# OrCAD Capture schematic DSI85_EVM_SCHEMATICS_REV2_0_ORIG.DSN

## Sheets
1 PAGE01 Title Page: title: PAGE01 SN65DSI85 EVM Schematics Block Diagram; rev: v2.0; note: YJL_DSI85EVM_rev2_0
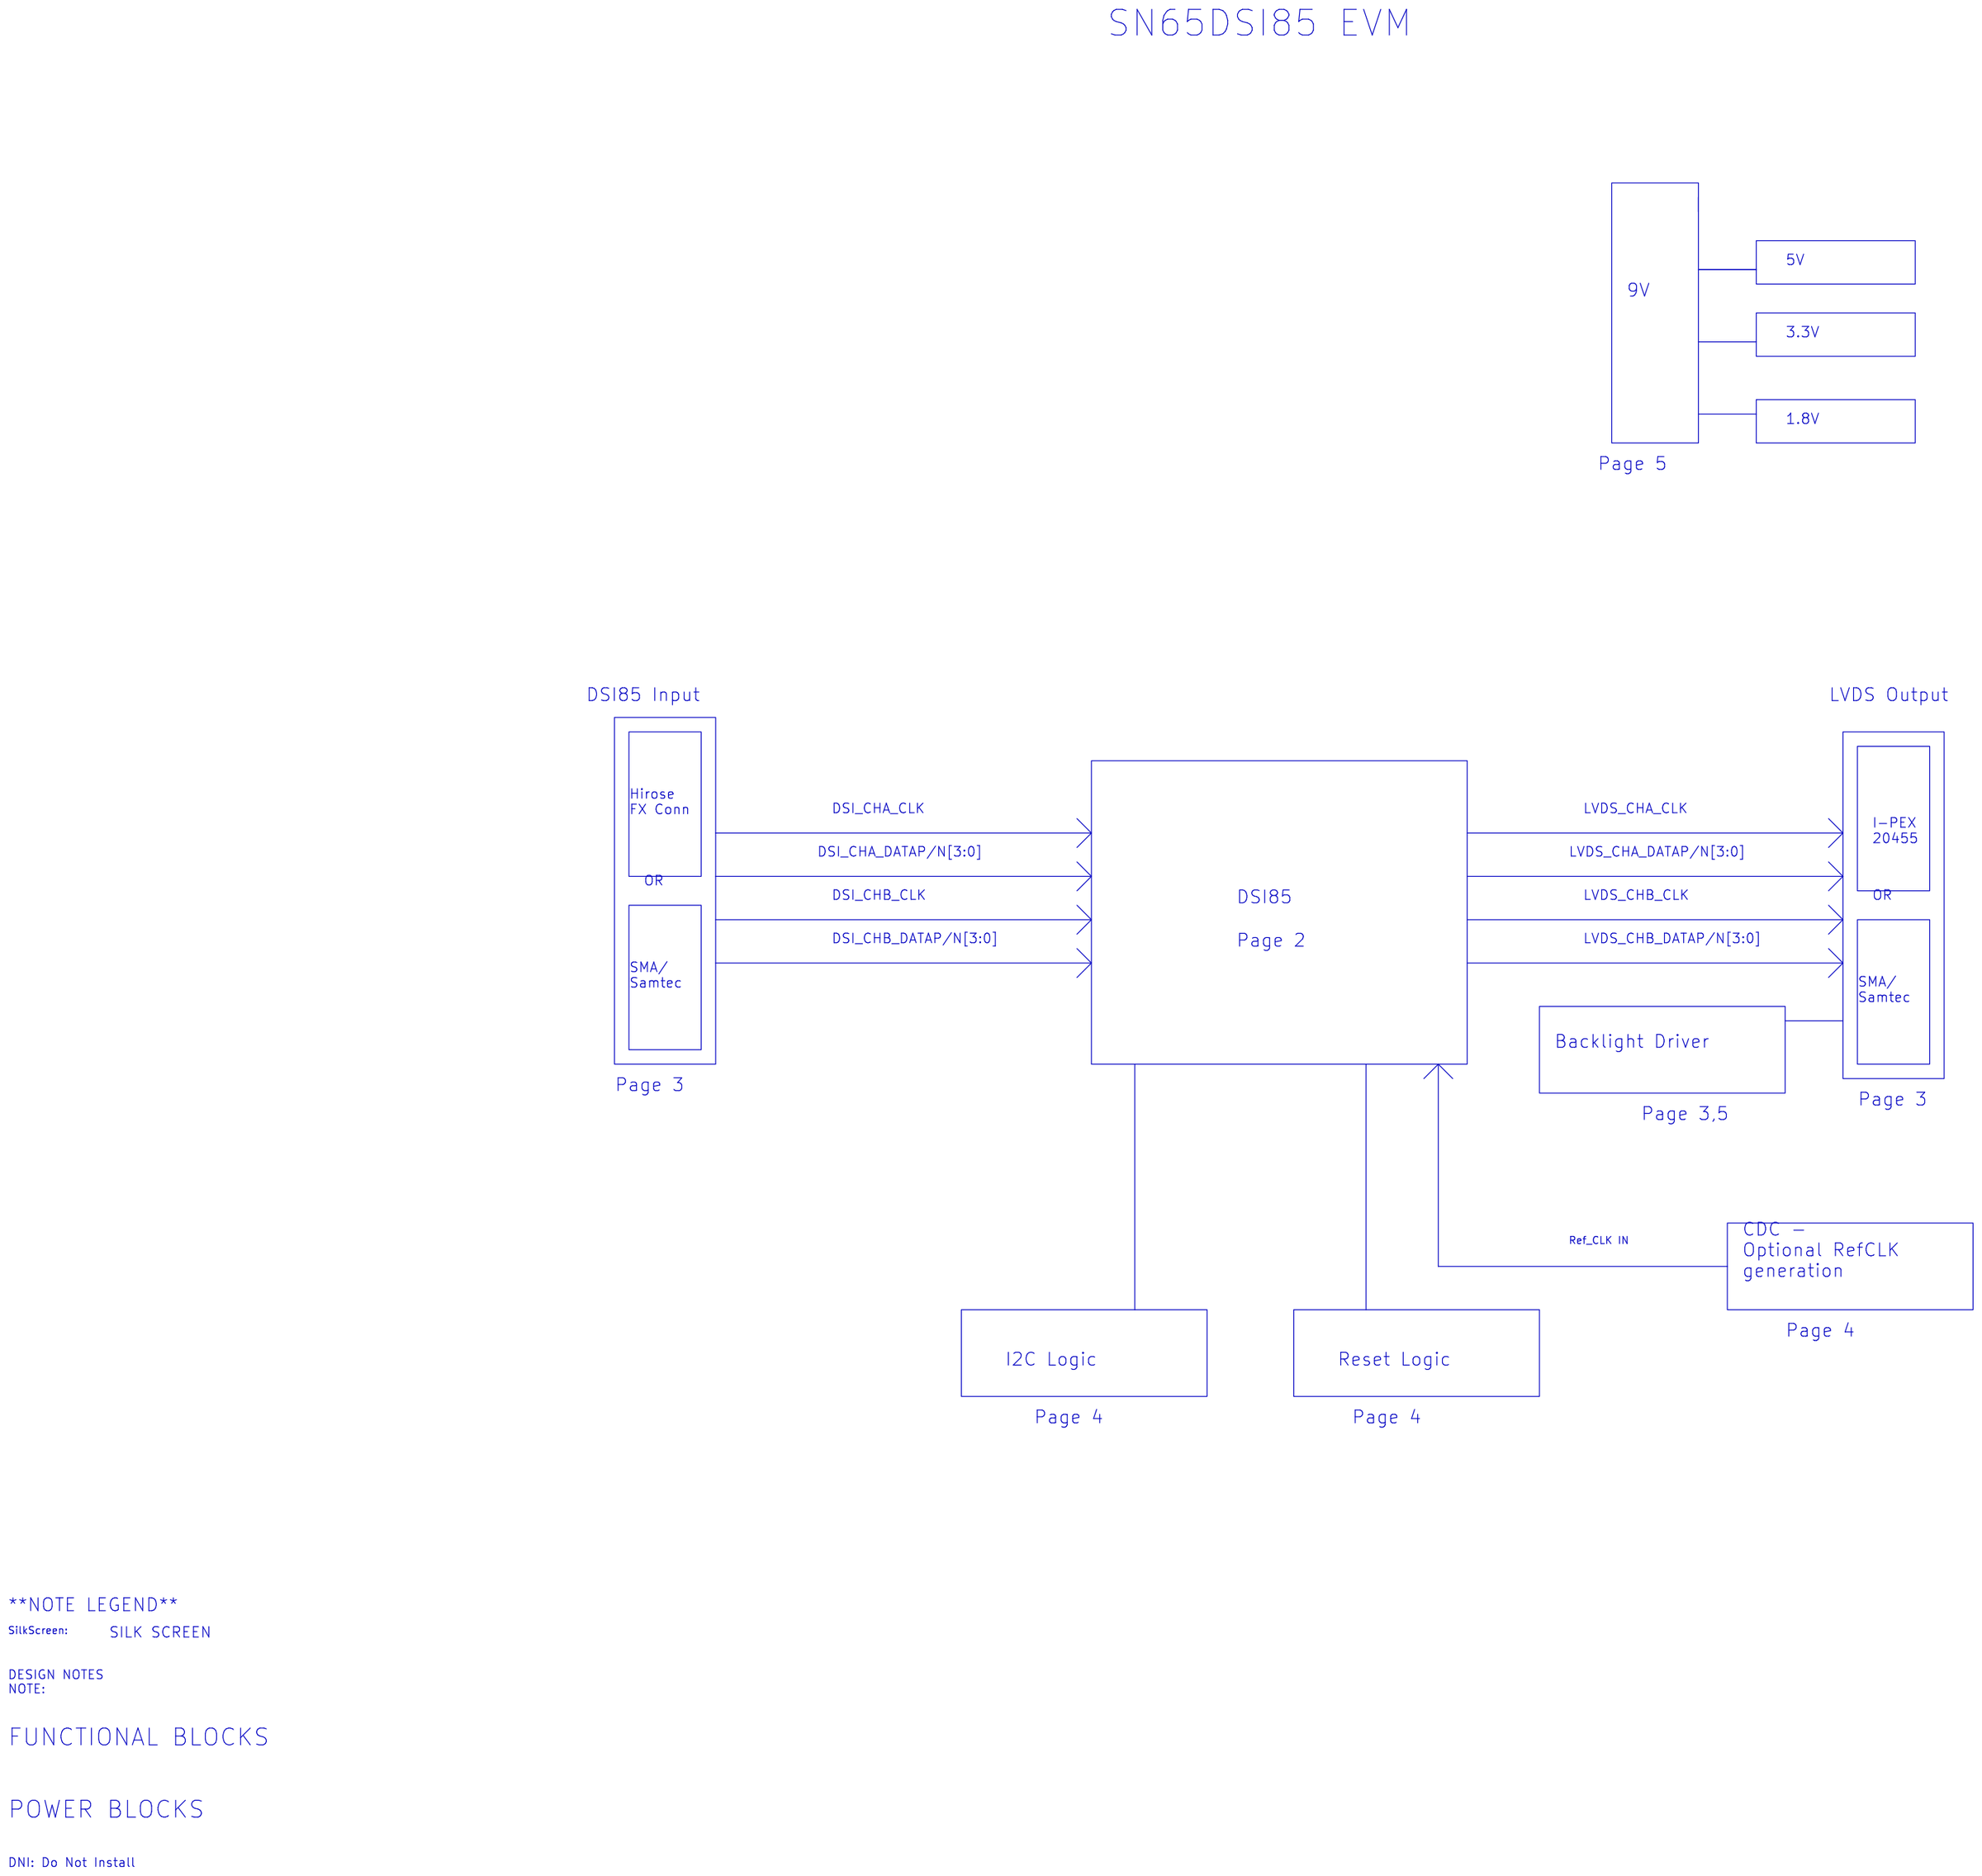
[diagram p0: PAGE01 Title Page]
2 PAGE02 DSI85: size C; title: PAGE02 SN65DSI85; note: Preliminary
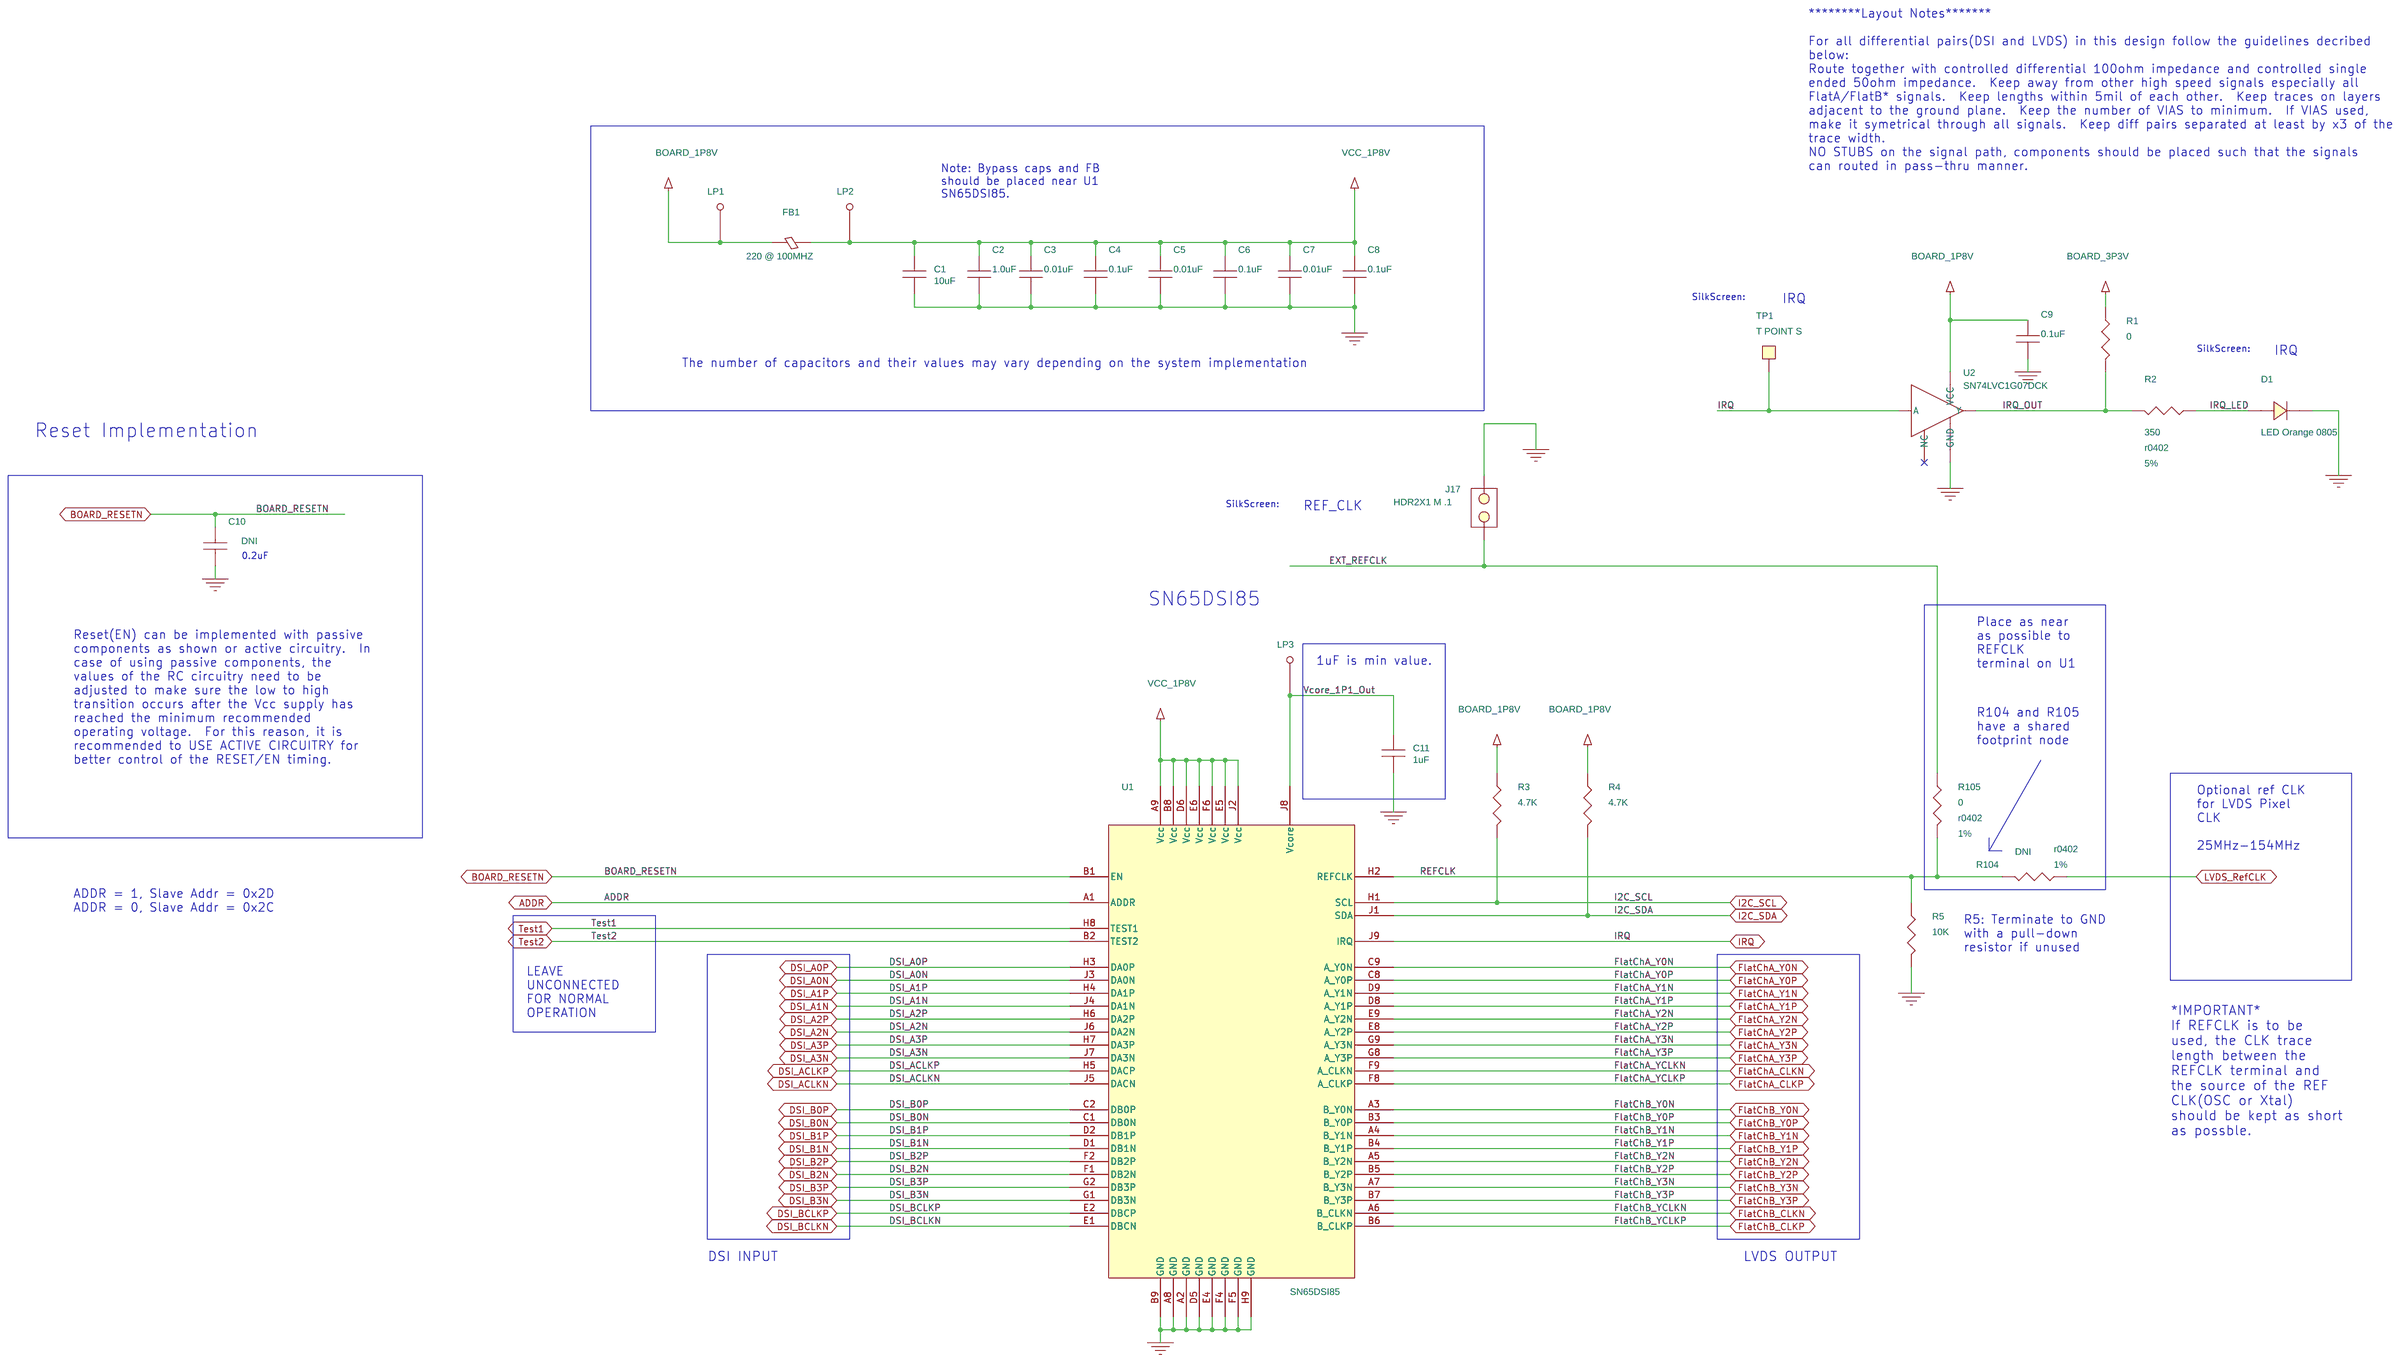
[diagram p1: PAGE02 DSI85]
3 PAGE03 Connectors: size C; title: PAGE03 Connectors
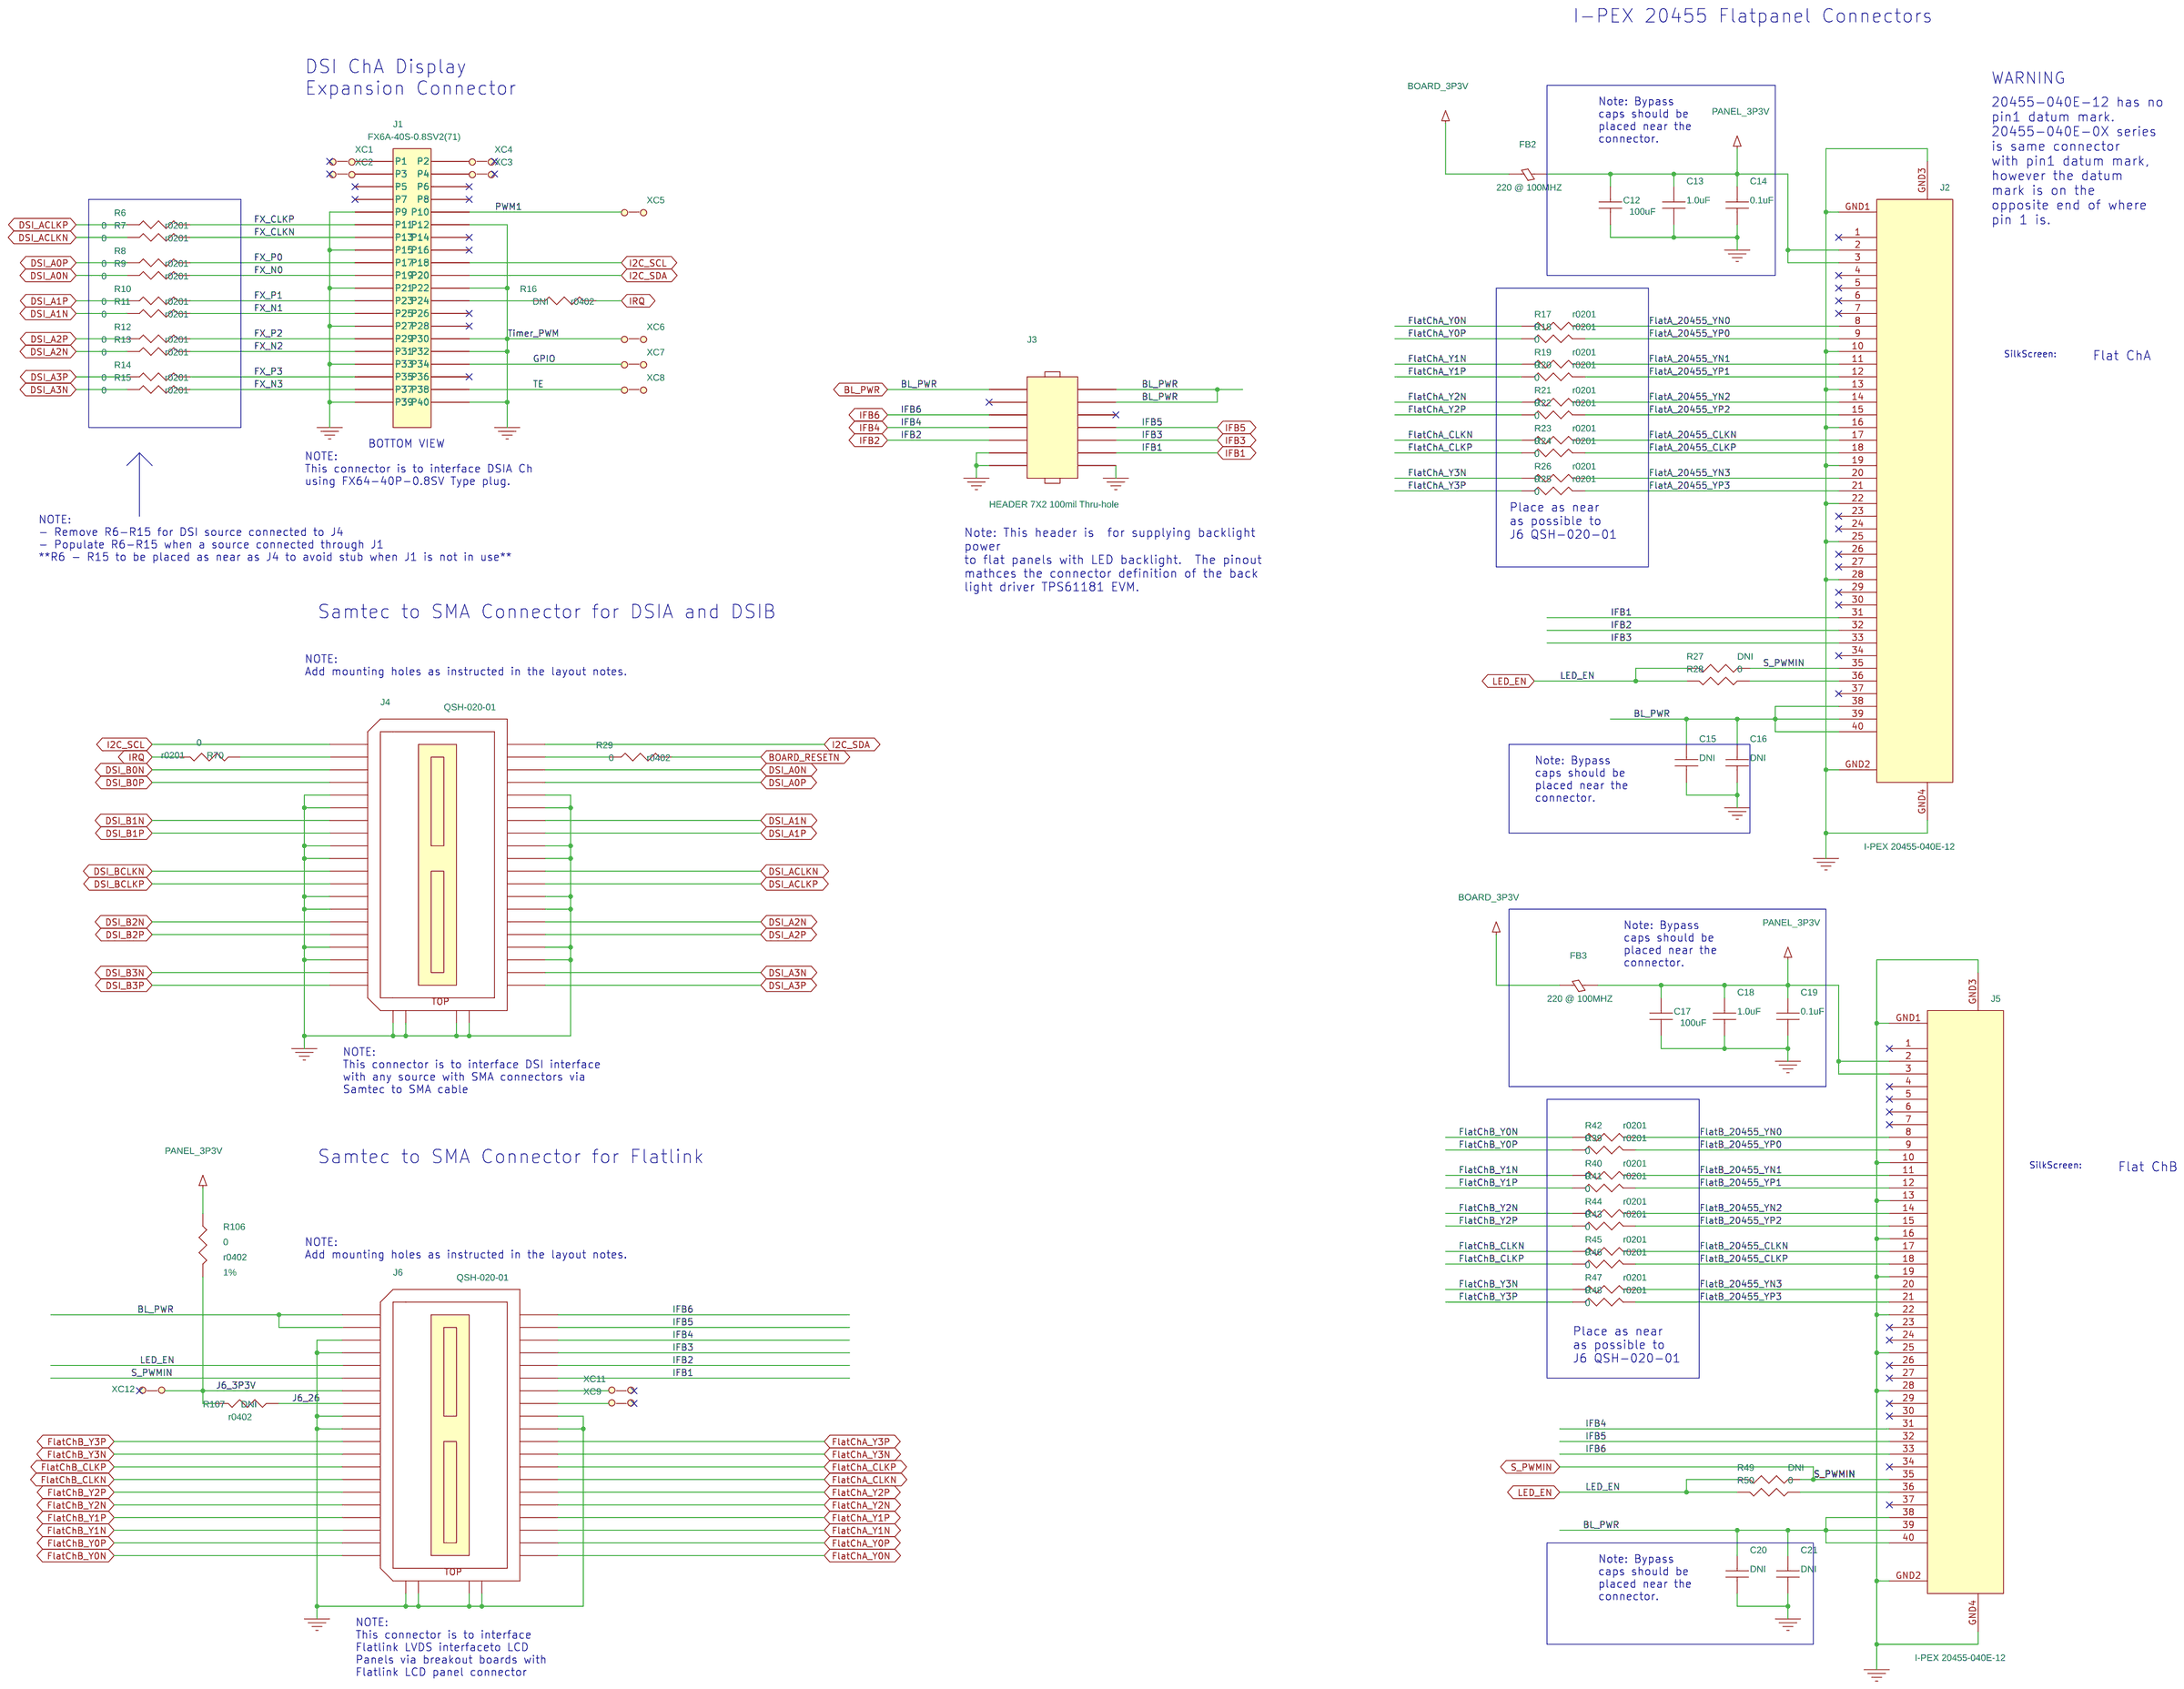
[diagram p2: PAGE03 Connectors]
4 PAGE04 Reset_CDC: size C; title: PAGE04 RESET_CDC
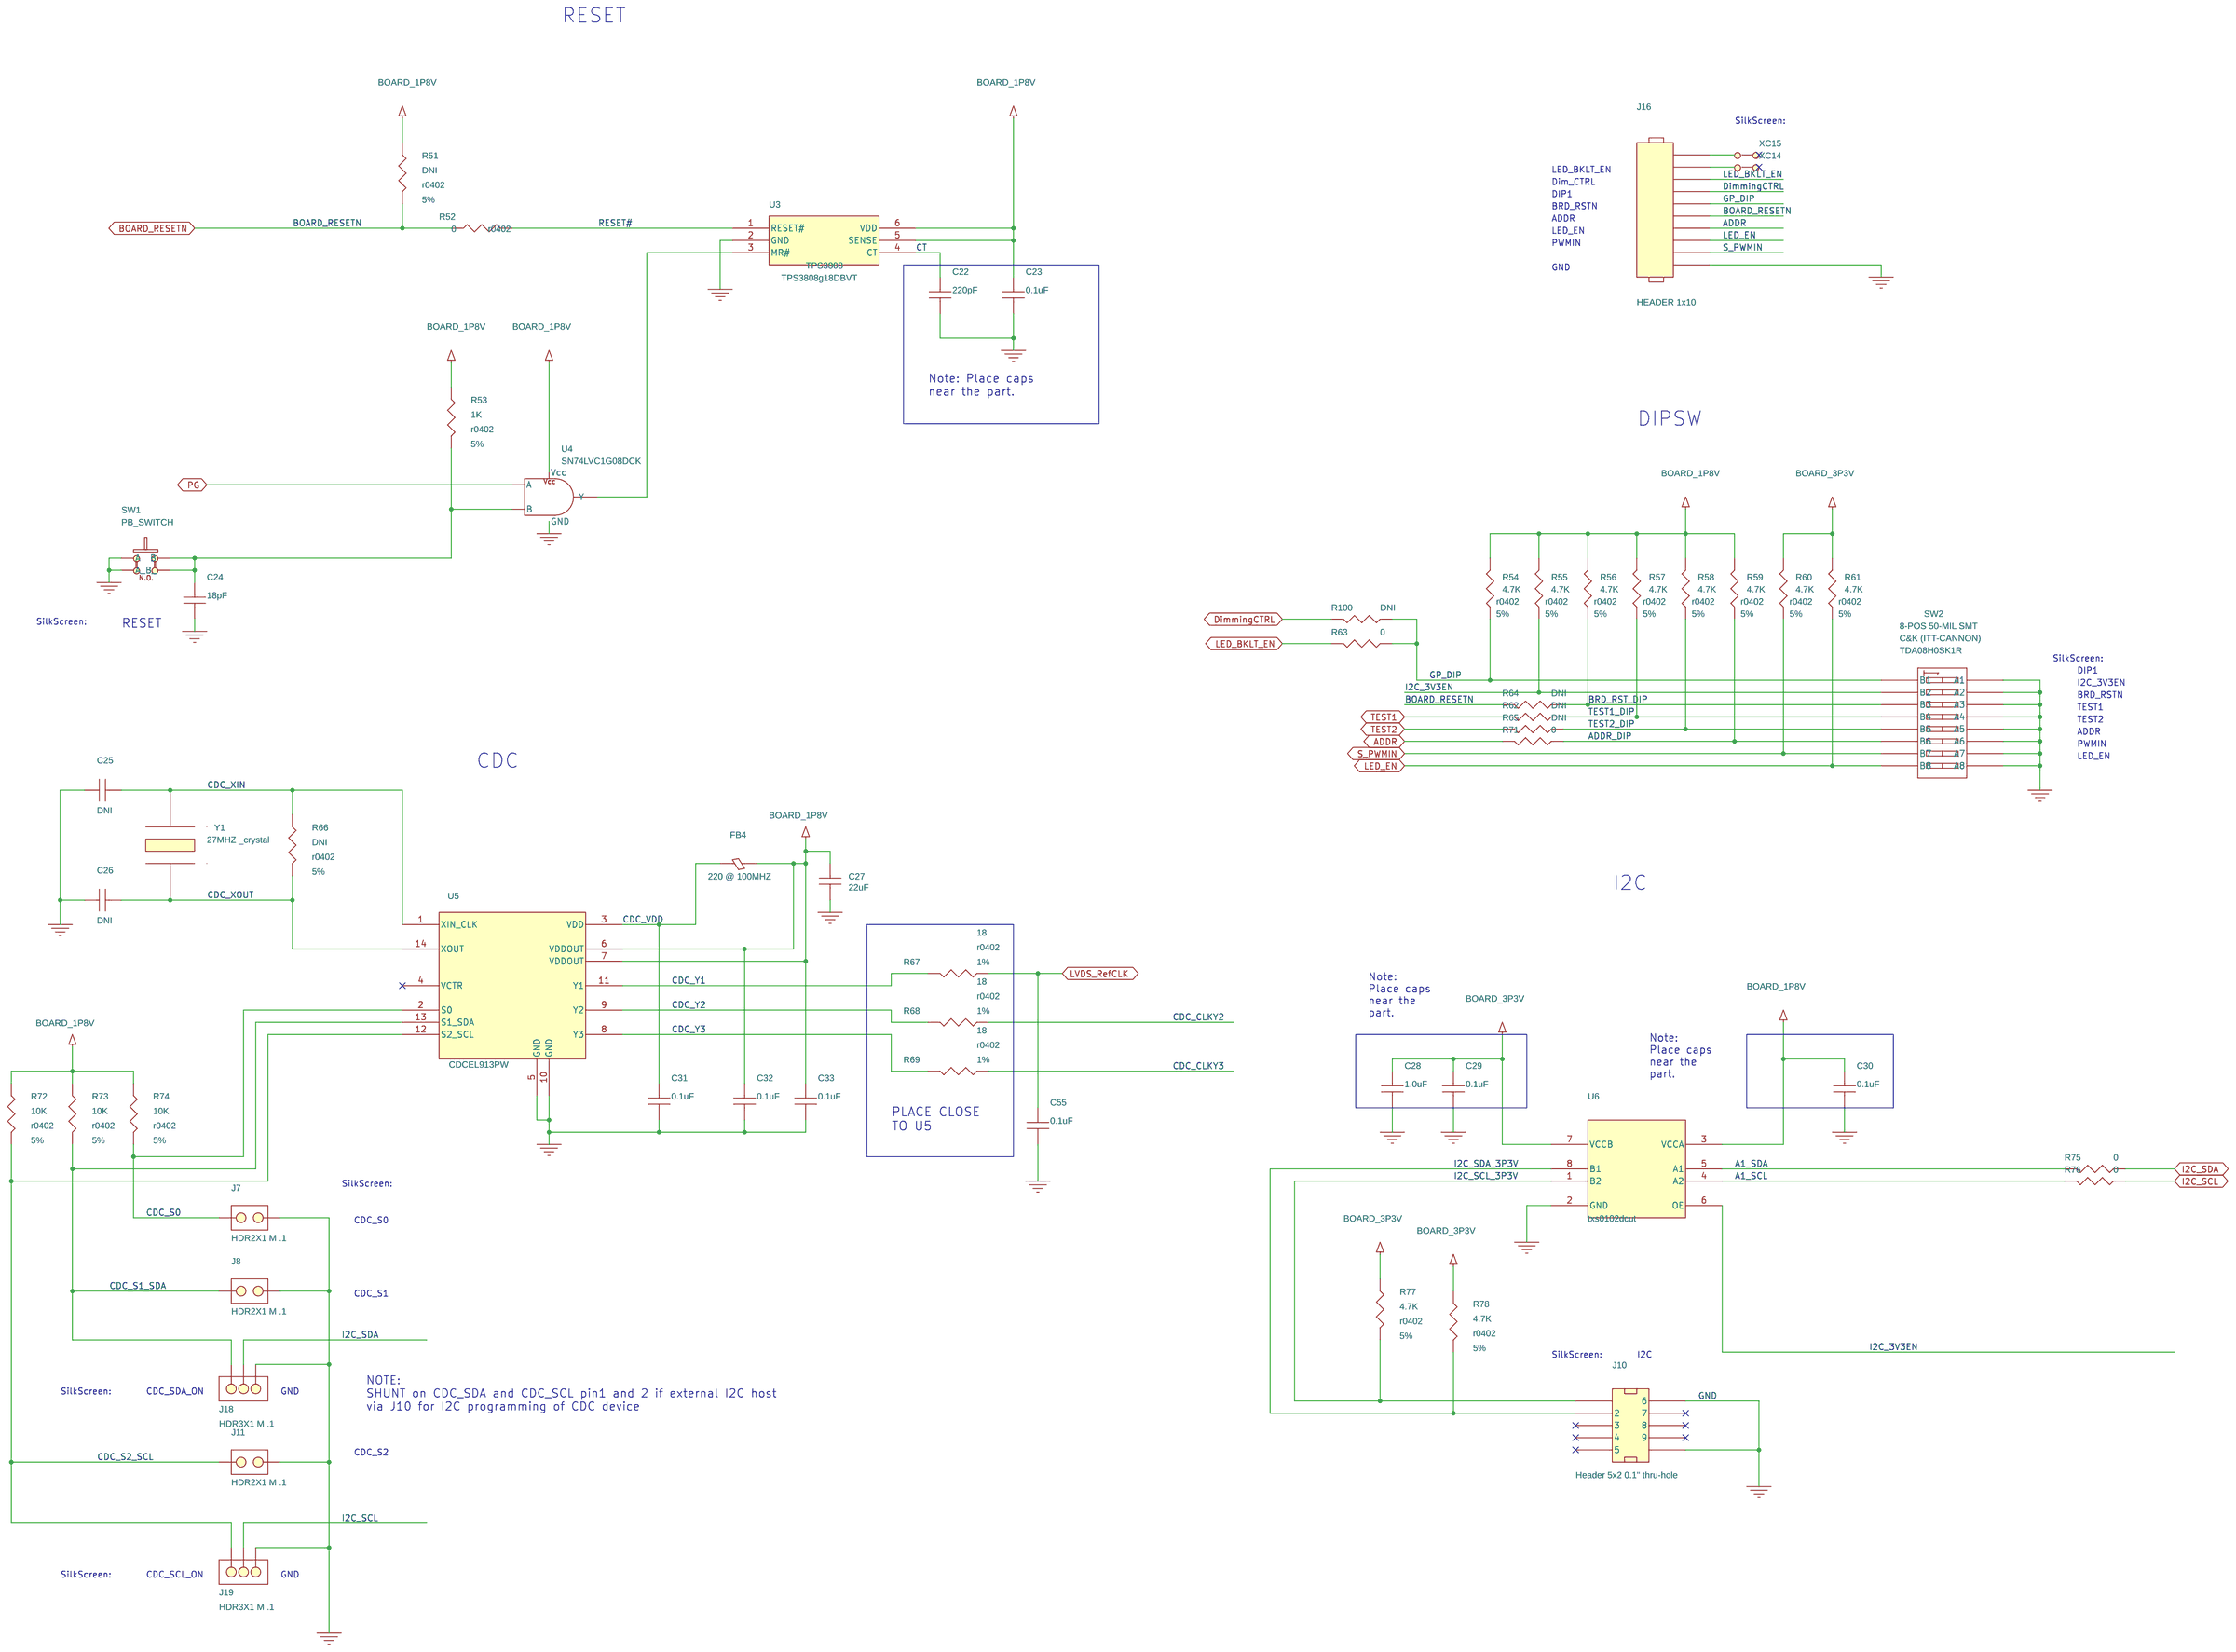
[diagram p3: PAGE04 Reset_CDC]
5 PAGE05 Power: size C; title: PAGE05 Power
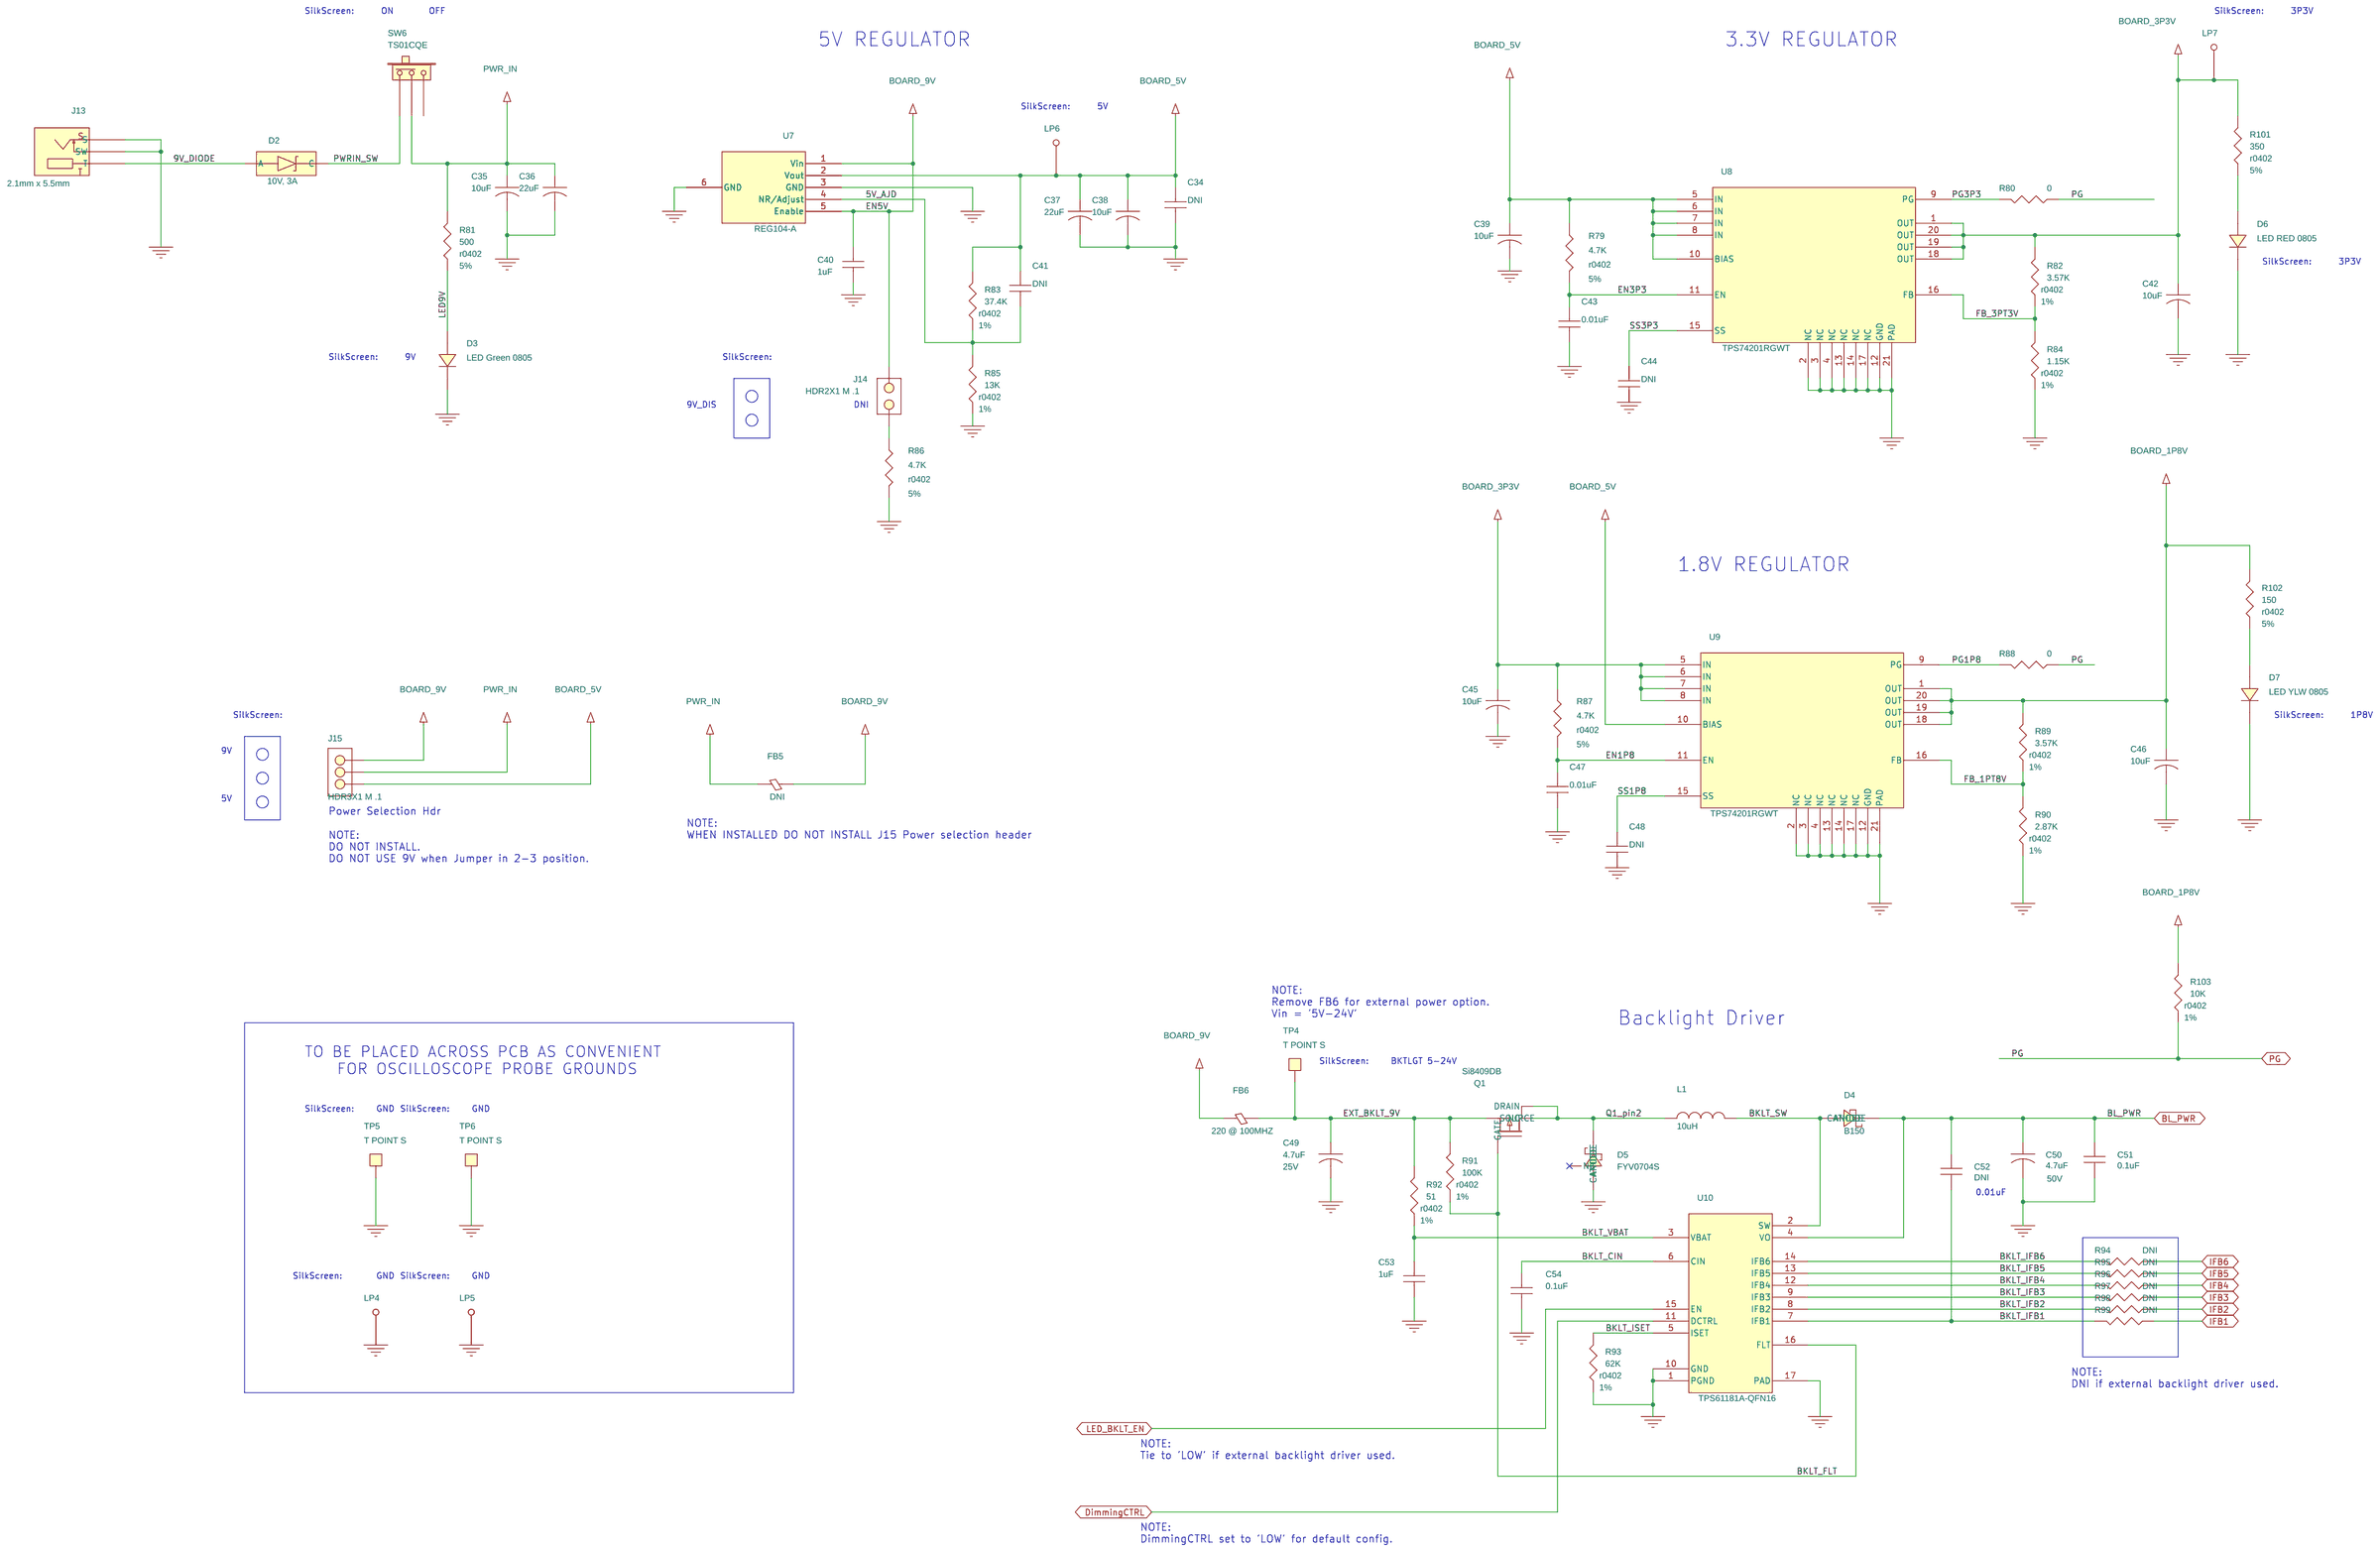
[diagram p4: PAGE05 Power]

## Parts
sheet PAGE02 DSI85
C1  10uF  [cc0805]
C2  1.0uF  [cc0402]
C3  0.01uF  [cc0201]
C4  0.1uF  [cc0201]
C5  0.01uF  [cc0201]
C6  0.1uF  [cc0201]
C7  0.01uF  [cc0201]
C8  0.1uF  [cc0201]
C9  0.1uF  [cc0201]
C10  DNI  [cc0201]
C11  1uF  [cc0603]
D1  LED Orange 0805  [cc0805]
FB1  220 @ 100MHZ  [r0603]
J17  HDR2X1 M .1  [berg1x2]
LP1  LP  [TESTLOOP]
LP2  LP  [TESTLOOP]
LP3  LP  [TESTLOOP]
R1  0  [r0402]
R2  350  [r0402]
R3  4.7K  [r0402]
R4  4.7K  [r0402]
R5  10K  [r0402]
R104  DNI  [r0402]
R105  0  [r0402]
TP1  T POINT S  [berg1x1]
U1  SN65DSI85  [Ironwood_81pin_7048]
U2  SN74LVC1G07DCK  [DCK5]
sheet PAGE03 Connectors
C12  100uF  [CC6032]
C13  1.0uF  [cc0402]
C14  0.1uF  [cc0402]
C15  DNI  [cc0603]
C16  DNI  [cc0603]
C17  100uF  [CC6032]
C18  1.0uF  [cc0402]
C19  0.1uF  [cc0402]
C20  DNI  [cc0603]
C21  DNI  [cc0603]
FB2  220 @ 100MHZ  [r0603]
FB3  220 @ 100MHZ  [r0603]
J1  FX6A-40S-0.8SV2(71)  [IPEX_20006_40pin]
J2  I-PEX 20455-040E-12  [ipex_20455_40pin]
J3  HEADER 7X2 100mil Thru-hole  [berg2x7]
J4  QSH-020-01  [QSH-020_x]
J5  I-PEX 20455-040E-12  [ipex_20455_40pin]
J6  QSH-020-01  [QSH-020_x]
R6  0  [r0201]
R7  0  [r0201]
R8  0  [r0201]
R9  0  [r0201]
R10  0  [r0201]
R11  0  [r0201]
R12  0  [r0201]
R13  0  [r0201]
R14  0  [r0201]
R15  0  [r0201]
R16  DNI  [r0402]
R17  0  [r0201]
R18  0  [r0201]
R19  0  [r0201]
R20  0  [r0201]
R21  0  [r0201]
R22  0  [r0201]
R23  0  [r0201]
R24  0  [r0201]
R25  0  [r0201]
R26  0  [r0201]
R27  DNI  [r0402]
R28  0  [r0402]
R29  0  [r0402]
R39  0  [r0201]
R40  0  [r0201]
R41  0  [r0201]
R42  0  [r0201]
R43  0  [r0201]
R44  0  [r0201]
R45  0  [r0201]
R46  0  [r0201]
R47  0  [r0201]
R48  0  [r0201]
R49  DNI  [r0402]
R50  0  [r0402]
R70  0  [r0201]
R106  0  [r0402]
R107  DNI  [r0402]
XC1  XC  [jmp_2p]
XC2  XC  [jmp_2p]
XC3  XC  [jmp_2p]
XC4  XC  [jmp_2p]
XC5  XC  [jmp_2p]
XC6  XC  [jmp_2p]
XC7  XC  [jmp_2p]
XC8  XC  [jmp_2p]
XC9  XC  [jmp_2p]
XC11  XC  [jmp_2p]
XC12  XC  [jmp_2p]
sheet PAGE04 Reset_CDC
C22  220pF  [cc0402]
C23  0.1uF  [cc0402]
C24  18pF  [cc0402]
C25  DNI  [cc0402]
C26  DNI  [cc0402]
C27  22uF  [cc0805]
C28  1.0uF  [cc0402]
C29  0.1uF  [cc0402]
C30  0.1uF  [cc0402]
C31  0.1uF  [cc0402]
C32  0.1uF  [cc0402]
C33  0.1uF  [cc0402]
C55  0.1uF  [cc0402]
FB4  220 @ 100MHZ  [r0603]
J7  HDR2X1 M .1  [HDR_2x1]
J8  HDR2X1 M .1  [HDR_2x1]
J10  Header 5x2 0.1" thru-hole  [berg2x5]
J11  HDR2X1 M .1  [HDR_2x1]
J16  HEADER 1x10  [berg1x10]
J18  HDR3X1 M .1  [berg1x3]
J19  HDR3X1 M .1  [berg1x3]
R51  DNI  [r0402]
R52  0  [r0402]
R53  1K  [r0402]
R54  4.7K  [r0402]
R55  4.7K  [r0402]
R56  4.7K  [r0402]
R57  4.7K  [r0402]
R58  4.7K  [r0402]
R59  4.7K  [r0402]
R60  4.7K  [r0402]
R61  4.7K  [r0402]
R62  DNI  [r0402]
R63  0  [r0402]
R64  DNI  [r0402]
R65  DNI  [r0402]
R66  DNI  [r0402]
R67  18  [r0402]
R68  18  [r0402]
R69  18  [r0402]
R71  0  [r0402]
R72  10K  [r0402]
R73  10K  [r0402]
R74  10K  [r0402]
R75  0  [r0402]
R76  0  [r0402]
R77  4.7K  [r0402]
R78  4.7K  [r0402]
R100  DNI  [r0402]
SW1  PB_SWITCH  [SW_MOM_2NO]
SW2  8-POS 50-MIL SMT  [TDA08H0SK1]
U3  TPS3808  [dbv_r-pdso-g6]
U4  SN74LVC1G08DCK  [DCK5]
U5  CDCEL913PW  [PW14]
U6  txs0102dcut  [DCU8]
XC14  XC  [jmp_2p]
XC15  XC  [jmp_2p]
Y1  27MHZ _crystal  [ABM8]
sheet PAGE05 Power
C34  DNI  [cc0603]
C35  10uF  [cc0805]
C36  22uF  [cc0805]
C37  22uF  [cc0805]
C38  10uF  [cc1210]
C39  10uF  [cc0805]
C40  1uF  [cc0402]
C41  DNI  [cc0603]
C42  10uF  [cc0805]
C43  0.01uF  [cc0402]
C44  DNI  [cc0402]
C45  10uF  [cc0805]
C46  10uF  [cc0805]
C47  0.01uF  [cc0402]
C48  DNI  [cc0402]
C49  4.7uF  [cc0805]
C50  4.7uF  [cc0805]
C51  0.1uF  [cc0603]
C52  DNI  [cc0603]
C53  1uF  [cc0603]
C54  0.1uF  [cc0603]
D2  10V, 3A  [SOD323]
D3  LED Green 0805  [r0805]
D4  B150  [SMB-B150]
D5  FYV0704S  [SOT23]
D6  LED RED 0805  [r0805]
D7  LED YLW 0805  [r0805]
FB5  DNI  [r1210]
FB6  220 @ 100MHZ  [r0603]
J13  2.1mm x 5.5mm  [PJ-202AH]
J14  HDR2X1 M .1  [berg1x2]
J15  HDR3X1 M .1  [berg1x3]
L1  10uH  [IND_CDPH4D19F]
LP4  LP  [TESTLOOP]
LP5  LP  [TESTLOOP]
LP6  LP  [TESTLOOP]
LP7  LP  [TESTLOOP]
Q1  Si8409DB  [MFP_4]
R79  4.7K  [r0402]
R80  0  [r0402]
R81  500  [r0402]
R82  3.57K  [r0402]
R83  37.4K  [r0402]
R84  1.15K  [r0402]
R85  13K  [r0402]
R86  4.7K  [r0402]
R87  4.7K  [r0402]
R88  0  [r0402]
R89  3.57K  [r0402]
R90  2.87K  [r0402]
R91  100K  [r0402]
R92  51  [r0402]
R93  62K  [r0402]
R94  DNI  [r0603]
R95  DNI  [r0603]
R96  DNI  [r0603]
R97  DNI  [r0603]
R98  DNI  [r0603]
R99  DNI  [r0603]
R101  350  [r0402]
R102  150  [r0402]
R103  10K  [r0402]
SW6  TS01CQE  [TS01CQE]
TP4  T POINT S  [berg1x1]
TP5  T POINT S  [berg1x1]
TP6  T POINT S  [berg1x1]
U7  REG104-A  [DCQ_R-PDSO-G6]
U8  TPS74201RGWT  [RGW20]
U9  TPS74201RGWT  [RGW20]
U10  TPS61181A-QFN16  [rte_16pin]

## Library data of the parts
C1-C10 C13-C16 C18-C33 C43 C44 C47 C48 C55 = CAP_NP
C11 = CAP_NP: Manuf: Panasonic; Manuf PN: PCF1132DKR-ND
D1 = DIODE: Manuf: Rohm; Manuf PN: SML-211DTT86
FB1-FB4 FB6 = FERRITE_BEAD: FBEAD 1000@100MHz; Device: BEAD1806; MFC: MuRata; Manuf: MuRata; Manuf PN: BLM18EG221SN1D; Part Number: BLM18EG221SN1D; Part#: BLM18EG221SN1D
J14 J17 = HDR2X1_M_.1
LP1-LP7 = TESTLOOP: Manuf: KOBIKONN; Manuf PN: 151-103-RC
R1-R29 R39-R66 R70-R81 R86-R88 R94-R102 = R_4: Tolerance: 5%
R67-R69 R82-R85 R89-R93 R103-R107 = R_4: Tolerance: 1%
TP1 TP4-TP6 = T_POINT_S
U1 = SN65DSI85
U2 = SN74LVC1G07_0
C12 C17 = CAP_NP: Manuf: Vishay; Manuf PN: TR3C107K010C0100
J1 = 111-1003780_1: INSTALLED: DNI
J2 J5 = IPEX_LVDS_Conn_1
J3 = HEADER_7X2_0
J4 J6 = QSH-020-01_3
XC1-XC9 XC11 XC12 XC14 XC15 = XCON_0
J7 = HDR2X1_M_.1: Device: HDR2x1_100MIL; Manuf: AMP; Manuf PN: 103321-2; Manufacturer: AMP; Manufacturer Part Number: 103321-2; Manufacturer's Part Number: 103321-2; Part Number: 103321-2; TI_Silktext: S0
J8 = HDR2X1_M_.1: Device: HDR2x1_100MIL; Manuf: AMP; Manuf PN: 103321-2; Manufacturer: AMP; Manufacturer Part Number: 103321-2; Manufacturer's Part Number: 103321-2; Part Number: 103321-2; TI_Silktext: S1_SDA
J10 = CONN_PCB_5x2-S
J11 = HDR2X1_M_.1: Device: HDR2x1_100MIL; Manuf: AMP; Manuf PN: 103321-2; Manufacturer: AMP; Manufacturer Part Number: 103321-2; Manufacturer's Part Number: 103321-2; Part Number: 103321-2; TI_Silktext: S2_SCL
J16 = HEADER_10
J15 J18 J19 = HDR3X1_M_.1
SW1 = PB_SWITCH_0: Manuf: OMRON; Manuf PN: B3SN-3012P; PART_NUMBER: BRD_RESETN; Part#: B3SN-3012P; TI_Silktext: BRD_RESETN
SW2 = SW_DIP-8_SM_0: Manuf: C&K(ITT-CANNON); Manuf PN: TDA08H0SK1R; Vendor: C&K (ITT-CANNON); Vendor Part Number: TDA08H0SK1R
U3 = TPS3808: Low Quiescent Current Supervisior Circuit (SOT23- 6Pin); Manufacturer: Texas Instruments; Manufacturer's Part#: TPS3808g18DBVT; Part#: eprt-pcom-00033-0000; Status: OK
U4 = SN74AHC1G08DCK_2
U5 = CDCEL913PW
U6 = txs0102dcut_2
Y1 = 27MHZ__crystal
C34 C41 = CAP_NP: Manuf: AVX; Manuf PN: 06033D104KAT2A
C35 C36 C39 C42 C45 C46 = CAP_0: CAP CER 10UF 6.3V 10% X5R 0805; Mfr: MURATA; PN: GRM21BR60J106KE19L; TN: 207-0208-000
C37 = CAP_0: CAP CER 10UF 6.3V 10% X5R 0805; Manuf: TDK; Manuf PN: C3216X5R0J226M; Mfr: MURATA; PN: GRM21BR60J106KE19L; TN: 207-0208-000
C38 = CAP_0: CAP CER 10UF 6.3V 10% X5R 0805; Manuf: TDK; Manuf PN: C3225X5R1E106M; Mfr: MURATA; PN: GRM21BR60J106KE19L; TN: 207-0208-000
C40 = cc0402
C49 = CAP_0: CAP CER 4.7UF 50V X5R 10% 0805; Mfr: TDK; PN: C2012X5R1H475K; TN: 111-1003847; Voltage: 25V
C50 = CAP_0: CAP CER 4.7UF 50V X5R 10% 0805; Mfr: TDK; PN: C2012X5R1H475K; TN: 111-1003847; Voltage: 50V
C51 = CAPACITOR_NON-POL: CAP CER .1UF 50V 10% X7R 0603; Mfr: MURATA; PN: GRM188R71H104KA93D; TN: 111-1003846
C52 = CAPACITOR_NON-POL: CAP CERM .01UF 10% 50V X7R 0603; Mfr: AVX; PN: 06035C103KAT2A; TN: 207-0014-000
C53 = CAPACITOR_NON-POL: CAP CER 1.0UF 16V 10% X5R 0603; Manuf: Murata; Manuf PN: GRM188R61E105KA12D; Mfr: MURATA; PN: GRM188R61C105KA93D; TN: 207-0259-000
C54 = 0.1uFCapacitor10V10%0402: Manuf: TDK; Manuf PN: C1608X7R1H104K
D2 = BAT60A
D3 = DIODE: Manuf: Arrow (Lumex); Manuf PN: 670-1006 (SML_LX0805GC); PART_NUMBER: PWR_5V; TI_Silktext: PWR_5V
D4 = DIODE_SCHOTTKY_0: DIODE SCHOTTKY 50V 2A SMB; Mfr: DIODES, INC; PN: B150-13-F; TN: 111-1003864
D5 = FYV0704S_SOT23: DIODE SCHOTTKY 40V 0.75A SOT-23; Mfr: FAIRCHILD; PN: FYV0704SMTF; TN: 111-1003865
D6 D7 = DIODE: Manuf: Rohm; Manuf PN: SML-211UT
FB5 = FB1210_0
J13 = BNC_2: MANUF: CUI STACK; PART_NUMBER: 5V_SUPPLY; TI_Silktext: 5V_SUPPLY
L1 = INDUCTOR: INDUCTOR 10UH 0.8A SHIELD SMD; Mfr: SUMIDA; PN: CDPH4D19FNP-100MC; TN: 111-1003866
Q1 = Si8409DB_0: MOSFET P-CH 30V 4.6A 2X2 4-MFP; Mfr: VISHAY; PN: SI8409DB-T1-E1; TN: 111-1003868
SW6 = SW_SLIDE_SPDT2: Manuf: C&K Div.; Manufacturer: C&K Div.; Part_Type: Switch\Slide
U7 = REG104_0
U8 U9 = TPS74401RGWT_0
U10 = TPS61181A-QFN16: IC LED DVR 6STRING NOTEBK 16WQFN; Mfr: TI; PN: TPS61181ARTET; TN: 111-1003871

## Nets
5V_AJD: C41.2 R83.1 R85.2 U7.4(NR/Adjust)
9V_DIODE: D2.2(A) J13.1(T)
GND: C1.2 C2.2 C3.2 C4.2 C5.2 C6.2 C7.2 C8.2 C9.2 C10.2 C11.2 C12.2 C13.2 C14.2 C15.2 C16.2 C17.2 C18.2 C19.2 C20.2 C21.2 C22.2 C23.2 C24.2 C25.1 C26.1 C27.2 C28.2 C29.2 C30.2 C31.2 C32.2 C33.2 C34.2 C35.2 C36.2 C37.2 C38.2 C39.2 C40.2 C42.2 C43.2 C44.2 C45.2 C46.2 C47.2 C48.2 C49.2 C50.2 C51.2 C53.2 C54.2 C55.2 D1.2(K) D3.2(K) D5.1(ANODE) D6.2(K) D7.2(K) J1.9(P9) J1.12(P12) J1.15(P15) J1.21(P21) J1.22(P22) J1.27(P27) J1.32(P32) J1.33(P33) J1.39(P39) J1.40(P40) J2.10 J2.13 J2.16 J2.19 J2.22 J2.25 J2.28 J2.GND1 J2.GND2 J2.GND3 J2.GND4 J3.12 J3.13 J3.14 J4.5 J4.6 J4.7 J4.8 J4.13 J4.14 J4.15 J4.16 J4.21 J4.22 J4.23 J4.24 J4.29 J4.30 J4.31 J4.32 J4.G1 J4.G2 J4.G3 J4.G4 J5.10 J5.13 J5.16 J5.19 J5.22 J5.25 J5.28 J5.GND1 J5.GND2 J5.GND3 J5.GND4 J6.21 J6.22 J6.23 J6.24 J6.34 J6.36 J6.G1 J6.G2 J6.G3 J6.G4 J7.2 J8.2 J10.2(6) J10.10 J11.2 J13.2(S) J13.3(SW) J16.10 J17.2 J18.3 J19.3 LP4.1 LP5.1 R5.2 R84.1 R85.1 R86.2 R90.1 R93.1 SW1.1(A) SW1.2(A_) SW2.1(A1) SW2.2(A2) SW2.3(A3) SW2.4(A4) SW2.5(A5) SW2.6(A6) SW2.7(A7) SW2.8(A8) TP5.1(TP) TP6.1(TP) U1.A2(GND) U1.A8(GND) U1.B9(GND) U1.D5(GND) U1.E4(GND) U1.F4(GND) U1.F5(GND) U1.H9(GND) U2.3(GND) U3.2(GND) U4.3(GND) U5.5(GND) U5.10(GND) U6.2(GND) U7.3(GND) U7.6(GND) U8.2(NC) U8.3(NC) U8.4(NC) U8.12(GND) U8.13(NC) U8.14(NC) U8.17(NC) U8.21(PAD) U9.2(NC) U9.3(NC) U9.4(NC) U9.12(GND) U9.13(NC) U9.14(NC) U9.17(NC) U9.21(PAD) U10.1(PGND) U10.10(GND) U10.17(PAD) Y1.2(GND) Y1.4(GND)
Vcc_1P8V: C1.1 C2.1 C3.1 C4.1 C5.1 C6.1 C7.1 C8.1 FB1.2 LP2.1 U1.A9(Vcc) U1.B8(Vcc) U1.D6(Vcc) U1.E5(Vcc) U1.E6(Vcc) U1.F6(Vcc) U1.J2(Vcc)
A1_SCL: R76.2 U6.4(A2)
A1_SDA: R75.2 U6.5(A1)
ADDR: J16.7 R71.2 U1.A1(ADDR)
ADDR_DIP: R59.1 R71.1 SW2.11(B6)
BKLT_CIN: C54.1 U10.6(CIN)
BKLT_FLT: Q1.1(GATE) R91.1 U10.16(FLT)
BKLT_IFB1: C52.2 R99.2 U10.7(IFB1)
BKLT_IFB2: R98.2 U10.8(IFB2)
BKLT_IFB3: R97.2 U10.9(IFB3)
BKLT_IFB4: R96.2 U10.12(IFB4)
BKLT_IFB5: R95.2 U10.13(IFB5)
BKLT_IFB6: R94.2 U10.14(IFB6)
BKLT_ISET: R93.2 U10.5(ISET)
BKLT_SW: D4.1(ANODE) L1.1 U10.2(SW)
BKLT_VBAT: C53.1 R92.1 U10.3(VBAT)
BL_PWR: C15.1 C16.1 C20.1 C21.1 C50.1 C51.1 C52.1 D4.2(CATHODE) J2.38 J2.39 J2.40 J3.1 J3.2 J3.3 J5.38 J5.39 J5.40 J6.38 J6.40 U10.4(VO)
BOARD_1P8V: C9.1 C23.1 C27.1 C30.1 C32.1 C33.1 C46.1 FB1.1 FB4.2 LP1.1 R3.1 R4.1 R51.1 R53.1 R54.2 R55.2 R56.2 R57.2 R58.2 R59.2 R72.1 R73.1 R74.1 R89.2 R102.2 R103.2 U2.5(VCC) U3.5(SENSE) U3.6(VDD) U4.5(Vcc) U5.6(VDDOUT) U5.7(VDDOUT) U6.3(VCCA) U9.1(OUT) U9.18(OUT) U9.19(OUT) U9.20(OUT)
BOARD_3P3V: C28.1 C29.1 C42.1 C45.1 FB2.1 FB3.1 LP7.1 R1.1 R60.2 R61.2 R77.1 R78.1 R82.2 R87.1 R101.2 U6.7(VCCB) U8.1(OUT) U8.18(OUT) U8.19(OUT) U8.20(OUT) U9.5(IN) U9.6(IN) U9.7(IN) U9.8(IN)
BOARD_5V: C34.1 C37.1 C38.1 C39.1 C41.1 J15.3 LP6.1 R79.1 R83.2 U7.2(Vout) U8.5(IN) U8.6(IN) U8.7(IN) U8.8(IN) U8.10(BIAS) U9.10(BIAS)
BOARD_9V: C40.1 FB5.2 FB6.1 J14.2 J15.1 U7.1(Vin) U7.5(Enable)
BOARD_RESETN: C10.1 J16.6 R29.2 R51.2 R52.1 R64.2 U1.B1(EN)
BRD_RST_DIP: R56.1 R64.1 SW2.14(B3)
CDC_CLKY2: R68.1
CDC_CLKY3: R69.1
CDC_S0: J7.1 R74.2 U5.2(S0)
CDC_S1_SDA: J8.1 J18.1 R73.2 U5.13(S1_SDA)
CDC_S2_SCL: J11.1 J19.1 R72.2 U5.12(S2_SCL)
CDC_VDD: C31.1 FB4.1 U5.3(VDD)
CDC_XIN: C25.2 R66.1 U5.1(XIN_CLK) Y1.3(XO)
CDC_XOUT: C26.2 R66.2 U5.14(XOUT) Y1.1(XI)
CDC_Y1: R67.2 U5.11(Y1)
CDC_Y2: R68.2 U5.9(Y2)
CDC_Y3: R69.2 U5.8(Y3)
CT: C22.1 U3.4(CT)
DimmingCTRL: J16.4 R100.2 U10.11(DCTRL)
DSI_A0N: J4.35 R9.1 U1.J3(DA0N)
DSI_A0P: J4.33 R8.1 U1.H3(DA0P)
DSI_A1N: J4.27 R11.1 U1.J4(DA1N)
DSI_A1P: J4.25 R10.1 U1.H4(DA1P)
DSI_A2N: J4.11 R13.1 U1.J6(DA2N)
DSI_A2P: J4.9 R12.1 U1.H6(DA2P)
DSI_A3N: J4.3 R15.1 U1.J7(DA3N)
DSI_A3P: J4.1 R14.1 U1.H7(DA3P)
DSI_ACLKN: J4.19 R7.1 U1.J5(DACN)
DSI_ACLKP: J4.17 R6.1 U1.H5(DACP)
DSI_B0N: J4.36 U1.C1(DB0N)
DSI_B0P: J4.34 U1.C2(DB0P)
DSI_B1N: J4.28 U1.D1(DB1N)
DSI_B1P: J4.26 U1.D2(DB1P)
DSI_B2N: J4.12 U1.F1(DB2N)
DSI_B2P: J4.10 U1.F2(DB2P)
DSI_B3N: J4.4 U1.G1(DB3N)
DSI_B3P: J4.2 U1.G2(DB3P)
DSI_BCLKN: J4.20 U1.E1(DBCN)
DSI_BCLKP: J4.18 U1.E2(DBCP)
EN1P8: C47.1 R87.2 U9.11(EN)
EN3P3: C43.1 R79.2 U8.11(EN)
EXT_BKLT_9V: C49.1 FB6.2 Q1.4(SOURCE) R91.2 R92.2 TP4.1(TP)
EXT_REFCLK: J17.1 R105.1
FB_1PT8V: R89.1 R90.2 U9.16(FB)
FB_3PT3V: R82.1 R84.2 U8.16(FB)
FlatA_20455_CLKN: J2.17 R23.2
FlatA_20455_CLKP: J2.18 R24.2
FlatA_20455_YN0: J2.8 R17.2
FlatA_20455_YN1: J2.11 R19.2
FlatA_20455_YN2: J2.14 R21.2
FlatA_20455_YN3: J2.20 R26.2
FlatA_20455_YP0: J2.9 R18.2
FlatA_20455_YP1: J2.12 R20.2
FlatA_20455_YP2: J2.15 R22.2
FlatA_20455_YP3: J2.21 R25.2
FlatB_20455_CLKN: J5.17 R45.2
FlatB_20455_CLKP: J5.18 R46.2
FlatB_20455_YN0: J5.8 R42.2
FlatB_20455_YN1: J5.11 R40.2
FlatB_20455_YN2: J5.14 R44.2
FlatB_20455_YN3: J5.20 R47.2
FlatB_20455_YP0: J5.9 R39.2
FlatB_20455_YP1: J5.12 R41.2
FlatB_20455_YP2: J5.15 R43.2
FlatB_20455_YP3: J5.21 R48.2
FlatChA_CLKN: J6.13 R23.1 U1.F9(A_CLKN)
FlatChA_CLKP: J6.15 R24.1 U1.F8(A_CLKP)
FlatChA_Y0N: J6.1 R17.1 U1.C9(A_Y0N)
FlatChA_Y0P: J6.3 R18.1 U1.C8(A_Y0P)
FlatChA_Y1N: J6.5 R19.1 U1.D9(A_Y1N)
FlatChA_Y1P: J6.7 R20.1 U1.D8(A_Y1P)
FlatChA_Y2N: J6.9 R21.1 U1.E9(A_Y2N)
FlatChA_Y2P: J6.11 R22.1 U1.E8(A_Y2P)
FlatChA_Y3N: J6.17 R26.1 U1.G9(A_Y3N)
FlatChA_Y3P: J6.19 R25.1 U1.G8(A_Y3P)
FlatChB_CLKN: J6.14 R45.1 U1.A6(B_CLKN)
FlatChB_CLKP: J6.16 R46.1 U1.B6(B_CLKP)
FlatChB_Y0N: J6.2 R42.1 U1.A3(B_Y0N)
FlatChB_Y0P: J6.4 R39.1 U1.B3(B_Y0P)
FlatChB_Y1N: J6.6 R40.1 U1.A4(B_Y1N)
FlatChB_Y1P: J6.8 R41.1 U1.B4(B_Y1P)
FlatChB_Y2N: J6.10 R44.1 U1.A5(B_Y2N)
FlatChB_Y2P: J6.12 R43.1 U1.B5(B_Y2P)
FlatChB_Y3N: J6.18 R47.1 U1.A7(B_Y3N)
FlatChB_Y3P: J6.20 R48.1 U1.B7(B_Y3P)
FX_CLKN: J1.13(P13) R7.2
FX_CLKP: J1.11(P11) R6.2
FX_N0: J1.19(P19) R9.2
FX_N1: J1.25(P25) R11.2
FX_N2: J1.31(P31) R13.2
FX_N3: J1.37(P37) R15.2
FX_P0: J1.17(P17) R8.2
FX_P1: J1.23(P23) R10.2
FX_P2: J1.29(P29) R12.2
FX_P3: J1.35(P35) R14.2
GP_DIP: J16.5 R54.1 R63.1 R100.1 SW2.16(B1)
GPIO: J1.34(P34) XC7.1
I2C_3V3EN: R55.1 SW2.15(B2) U6.6(OE)
I2C_SCL: J1.18(P18) J4.40 J19.2 R3.2 R76.1 U1.H1(SCL)
I2C_SCL_3P3V: J10.1 R77.2 U6.1(B2)
I2C_SDA: J1.20(P20) J4.39 J18.2 R4.2 R75.1 U1.J1(SDA)
I2C_SDA_3P3V: J10.3(2) R78.2 U6.8(B1)
IFB1: J2.31 J3.11 J6.29 R99.1
IFB2: J2.32 J3.10 J6.31 R98.1
IFB3: J2.33 J3.9 J6.33 R97.1
IFB4: J3.8 J5.31 J6.35 R96.1
IFB5: J3.7 J5.32 J6.37 R95.1
IFB6: J3.6 J5.33 J6.39 R94.1
IRQ: R16.2 R70.2 TP1.1(TP) U1.J9(IRQ) U2.2(A)
IRQ_LED: D1.1(A) R2.1
IRQ_OUT: R1.2 R2.2 U2.4(Y)
J6_3P3V: J6.28 R106.2 R107.2 XC12.1
J6_26: J6.26 R107.1
LED9V: D3.1(A) R81.1
LED_BKLT_EN: J16.3 R63.2 U10.15(EN)
LED_EN: J6.32 J16.8 R27.2 R28.2 R49.2 R50.2 R61.1 SW2.9(B8)
LVDS_RefCLK: C55.1 R67.1 R104.1
Panel_3P3V: C12.1 C13.1 C14.1 C17.1 C18.1 C19.1 FB2.2 FB3.2 J2.2 J2.3 J5.2 J5.3 R106.1
PG: R80.1 R88.1 R103.1 U4.1(A)
PG1P8: R88.2 U9.9(PG)
PG3P3: R80.2 U8.9(PG)
PWM1: J1.10(P10) XC5.1
PWR_IN: C35.1 C36.1 FB5.1 J15.2 R81.2 SW6.2
PWRIN_SW: D2.1(C) SW6.1
Q1_pin2: D5.3(CATHODE) L1.2 Q1.2(NC) Q1.3(DRAIN)
REFCLK: R5.1 R104.2 R105.2 U1.H2(REFCLK)
RESET#: R52.2 U3.1(RESET#)
S_PWMIN: J2.35 J5.35 J6.30 J16.9 R27.1 R49.1 R60.1 SW2.10(B7)
SS1P8: C48.1 U9.15(SS)
SS3P3: C44.1 U8.15(SS)
TE: J1.38(P38) XC8.1
TEST1: R62.2 U1.H8(TEST1)
TEST1_DIP: R57.1 R62.1 SW2.13(B4)
TEST2: R65.2 U1.B2(TEST2)
TEST2_DIP: R58.1 R65.1 SW2.12(B5)
Timer_PWM: J1.30(P30) XC6.1
Vcore_1P1_Out: C11.1 LP3.1 U1.J8(Vcore)
N15262521: J1.24(P24) R16.1
N16337340: U3.3(MR#) U4.4(Y)
N16337368: C24.1 R53.2 SW1.3(B_) SW1.4(B) U4.2(B)
N16343227: J2.36 R28.1
N16438569: J14.1 R86.1
N16449790: J5.36 R50.1
N16485912: D6.1(A) R101.1
N16486116: D7.1(A) R102.1
N16547062: J6.27 XC11.2
N16547066: J6.25 XC9.2
N16553551: J4.38 R70.1
N16621879: J16.1 XC15.1
N16621883: J16.2 XC14.1
N16649721: J4.37 R29.1
N16671630: J1.4(P4) XC3.1
N16671631: J1.2(P2) XC4.1
N16671632: J1.1(P1) XC1.2
N16671633: J1.3(P3) XC2.2

Not connected (* = marked no-connect by the designer): D5 2(NC)*; J1 5(P5)* 6(P6)* 7(P7)* 8(P8)* 14(P14)* 16(P16)* 26(P26)* 28(P28)* 36(P36)*; J2 1* 4* 5* 6* 7* 23* 24* 26* 27* 29* 30* 34* 37*; J3 4* 5*; J5 1* 4* 5* 6* 7* 23* 24* 26* 27* 29* 30* 34* 37*; J10 4(7)* 5(3)* 6(8)* 7(4)* 8(9)* 9(5)*; SW6 3; U2 1(NC)*; U5 4(VCTR)*; XC1 1*; XC2 1*; XC3 2*; XC4 2*; XC5 2; XC6 2; XC7 2; XC8 2; XC9 1*; XC11 1*; XC12 2*; XC14 2*; XC15 2*

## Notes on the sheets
sheet 1
- SN65DSI85 EVM
- 5V
- 9V
- 3.3V
- 1.8V
- Page 5
- DSI85 Input
- LVDS Output
- Hirose
  FX Conn
- DSI_CHA_CLK
- LVDS_CHA_CLK
- I-PEX
  20455
- DSI_CHA_DATAP/N[3:0]
- LVDS_CHA_DATAP/N[3:0]
- OR
- DSI_CHB_CLK
- DSI85
- LVDS_CHB_CLK
- OR
- DSI_CHB_DATAP/N[3:0]
- Page 2
- LVDS_CHB_DATAP/N[3:0]
- SMA/
  Samtec
- SMA/
  Samtec
- Backlight Driver
- Page 3
- Page 3
- Page 3,5
- CDC -
  Optional RefCLK
  generation
- Ref_CLK IN
- Page 4
- I2C Logic
- Reset Logic
- Page 4
- Page 4
- **NOTE LEGEND**
- SilkScreen:
- SILK SCREEN
- DESIGN NOTES
  NOTE:
- FUNCTIONAL BLOCKS
- POWER BLOCKS
- DNI: Do Not Install
sheet 2
- ********Layout Notes*******
  For all differential pairs(DSI and LVDS) in this design follow the guidelines decribed
  below:
  Route together with controlled differential 100ohm impedance and controlled single
  ended 50ohm impedance.  Keep away from other high speed signals especially all
  FlatA/FlatB* signals.  Keep lengths within 5mil of each other.  Keep traces on layers
  adjacent to the ground plane.  Keep the number of VIAS to minimum.  If VIAS used,
  make it symetrical through all signals.  Keep diff pairs separated at least by x3 of the
  trace width.
  NO STUBS on the signal path, components should be placed such that the signals
  can routed in pass-thru manner.
- Note: Bypass caps and FB
  should be placed near U1
  SN65DSI85.
- SilkScreen:
- IRQ
- SilkScreen:
- IRQ
- The number of capacitors and their values may vary depending on the system implementation
- Reset Implementation
- SilkScreen:
- REF_CLK
- 0.2uF
- SN65DSI85
- Place as near
  as possible to
  REFCLK
  terminal on U1
- Reset(EN) can be implemented with passive
  components as shown or active circuitry.  In
  case of using passive components, the
  values of the RC circuitry need to be
  adjusted to make sure the low to high
  transition occurs after the Vcc supply has
  reached the minimum recommended
  operating voltage.  For this reason, it is
  recommended to USE ACTIVE CIRCUITRY for
  better control of the RESET/EN timing.
- 1uF is min value.
- R104 and R105
  have a shared
  footprint node
- Optional ref CLK
  for LVDS Pixel
  CLK
  25MHz-154MHz
- ADDR = 1, Slave Addr = 0x2D
  ADDR = 0, Slave Addr = 0x2C
- R5: Terminate to GND
  with a pull-down
  resistor if unused
- LEAVE
  UNCONNECTED
  FOR NORMAL
  OPERATION
- *IMPORTANT*
  If REFCLK is to be
  used, the CLK trace
  length between the
  REFCLK terminal and
  the source of the REF
  CLK(OSC or Xtal)
  should be kept as short
  as possble.
- DSI INPUT
- LVDS OUTPUT
sheet 3
- I-PEX 20455 Flatpanel Connectors
- DSI ChA Display
  Expansion Connector
- WARNING
- Note: Bypass
  caps should be
  placed near the
  connector.
- 20455-040E-12 has no
  pin1 datum mark.
  20455-040E-0X series
  is same connector
  with pin1 datum mark,
  however the datum
  mark is on the
  opposite end of where
  pin 1 is.
- SilkScreen:
- Flat ChA
- BOTTOM VIEW
- NOTE:
  This connector is to interface DSIA Ch
  using FX64-40P-0.8SV Type plug.
- Place as near
  as possible to
  J6 QSH-020-01
- NOTE:
  - Remove R6-R15 for DSI source connected to J4
  - Populate R6-R15 when a source connected through J1
  **R6 - R15 to be placed as near as J4 to avoid stub when J1 is not in use**
- Note: This header is  for supplying backlight
  power
  to flat panels with LED backlight.  The pinout
  mathces the connector definition of the back
  light driver TPS61181 EVM.
- Samtec to SMA Connector for DSIA and DSIB
- NOTE:
  Add mounting holes as instructed in the layout notes.
- Note: Bypass
  caps should be
  placed near the
  connector.
- Note: Bypass
  caps should be
  placed near the
  connector.
- NOTE:
  This connector is to interface DSI interface
  with any source with SMA connectors via
  Samtec to SMA cable
- Samtec to SMA Connector for Flatlink
- SilkScreen:
- Flat ChB
- NOTE:
  Add mounting holes as instructed in the layout notes.
- Place as near
  as possible to
  J6 QSH-020-01
- Note: Bypass
  caps should be
  placed near the
  connector.
- NOTE:
  This connector is to interface
  Flatlink LVDS interfaceto LCD
  Panels via breakout boards with
  Flatlink LCD panel connector
sheet 4
- RESET
- SilkScreen:
- LED_BKLT_EN
- Dim_CTRL
- DIP1
- ADDR
- BRD_RSTN
- LED_EN
- PWMIN
- GND
- Note: Place caps
  near the part.
- DIPSW
- SilkScreen:
- RESET
- SilkScreen:
- DIP1
- BRD_RSTN
- I2C_3V3EN
- TEST1
- TEST2
- ADDR
- PWMIN
- CDC
- LED_EN
- I2C
- Note:
  Place caps
  near the
  part.
- Note:
  Place caps
  near the
  part.
- PLACE CLOSE
  TO U5
- SilkScreen:
- CDC_S0
- CDC_S1
- SilkScreen:
- I2C
- NOTE:
  SHUNT on CDC_SDA and CDC_SCL pin1 and 2 if external I2C host
  via J10 for I2C programming of CDC device
- SilkScreen:
- CDC_SDA_ON
- GND
- CDC_S2
- SilkScreen:
- CDC_SCL_ON
- GND
sheet 5
- SilkScreen:
- ON
- OFF
- SilkScreen:
- 3P3V
- 5V REGULATOR
- 3.3V REGULATOR
- SilkScreen:
- 5V
- SilkScreen:
- 3P3V
- SilkScreen:
- 9V
- SilkScreen:
- 9V_DIS
- DNI
- 1.8V REGULATOR
- SilkScreen:
- SilkScreen:
- 1P8V
- 9V
- 5V
- Power Selection Hdr
- NOTE:
  WHEN INSTALLED DO NOT INSTALL J15 Power selection header
- NOTE:
  DO NOT INSTALL.
  DO NOT USE 9V when Jumper in 2-3 position.
- NOTE:
  Remove FB6 for external power option.
  Vin = '5V-24V'
- Backlight Driver
- TO BE PLACED ACROSS PCB AS CONVENIENT
      FOR OSCILLOSCOPE PROBE GROUNDS
- SilkScreen:
- BKTLGT 5-24V
- SilkScreen:
- GND
- SilkScreen:
- GND
- 0.01uF
- SilkScreen:
- GND
- SilkScreen:
- GND
- NOTE:
  DNI if external backlight driver used.
- NOTE:
  Tie to 'LOW' if external backlight driver used.
- NOTE:
  DimmingCTRL set to 'LOW' for default config.
